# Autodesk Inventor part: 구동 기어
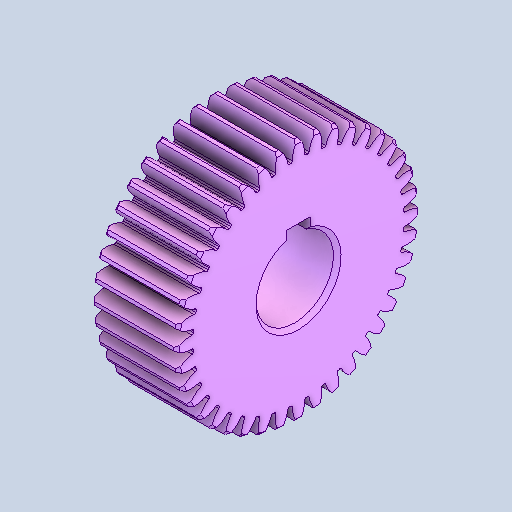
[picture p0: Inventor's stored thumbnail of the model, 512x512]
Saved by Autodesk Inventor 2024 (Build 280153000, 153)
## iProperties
Created: 2025-11
Part Number: 구동 기어
Material: 강철, 합금
Document SubType Name: Modeling
Designer: Edu07
Density: 7.73 g/cm^3
Appearance: 기본값
Author: jhkim
Sending System: Autodesk Inventor 2026
Preprocessor: ST-DEVELOPER v20.1
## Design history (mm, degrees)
node "구동 기어1"
node "솔리드2"
node "솔리드1"
